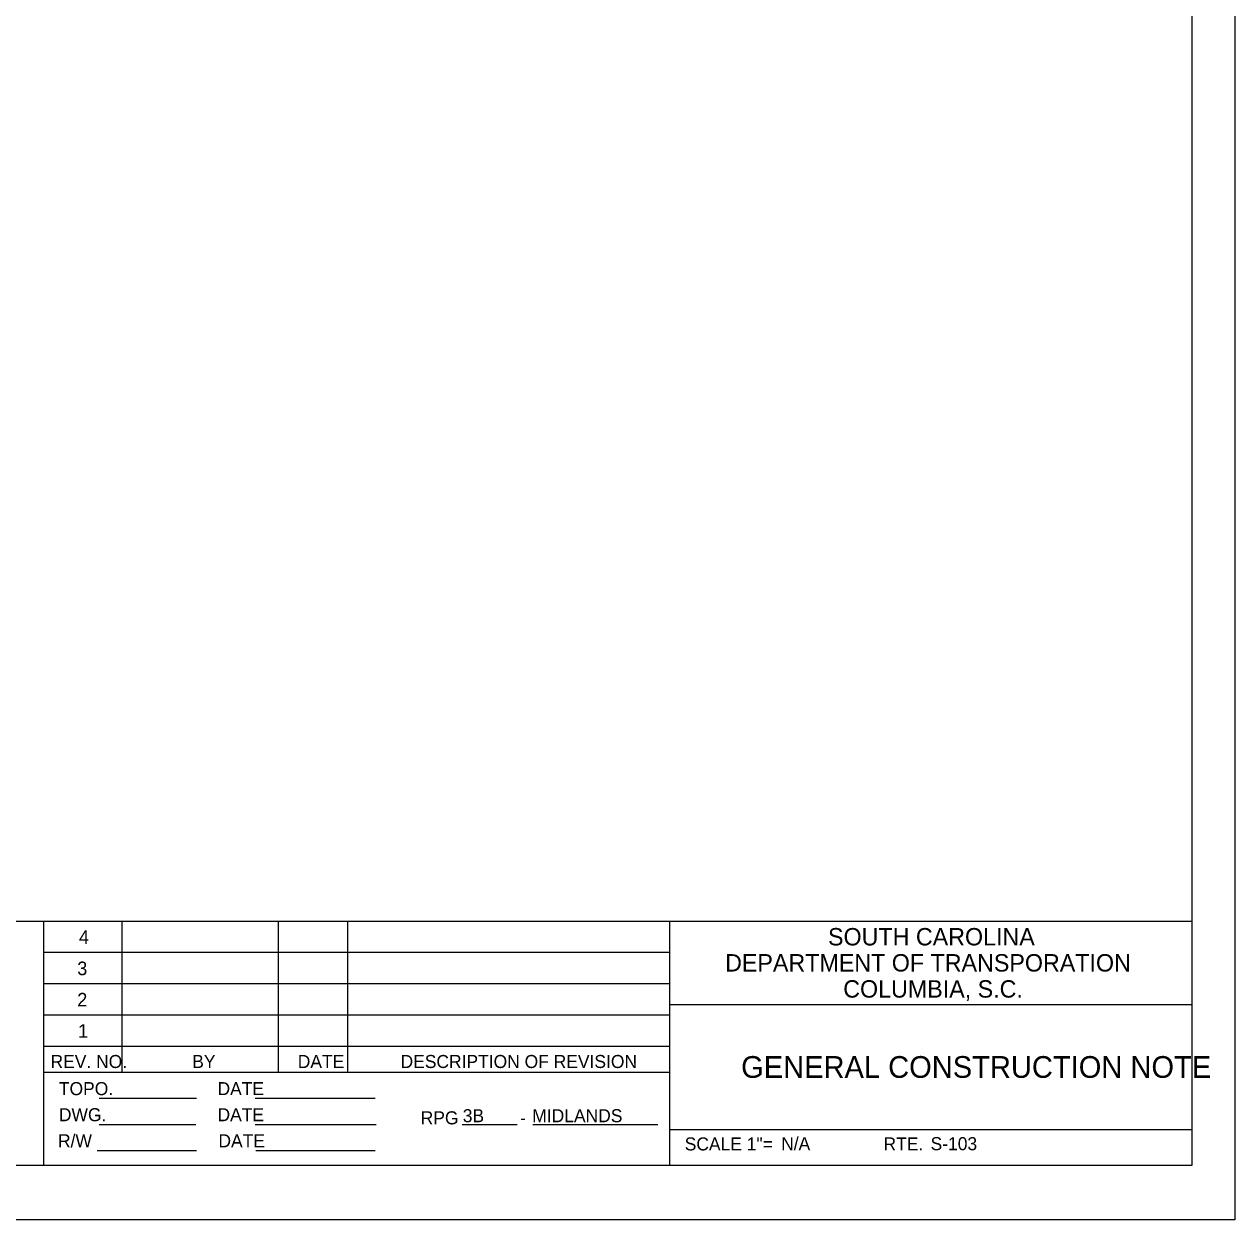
# Model space of a CAD drawing. Extents: x -796 to 2793, y -4650 to 4425.
# Drawn here: x 2221 to 2777, y -3500 to -2950 of the extents above; entities that cross this region are included whole.
import ezdxf

# ---------------------------------------------------------------- set-up
doc = ezdxf.new("R2010")
doc.units = 0
for name, color, linetype in [('RD_HC_CL', 7, 'Continuous'), ('RD_HC_Data', 7, 'Continuous'), ('RD_HC_Data_Tic', 7, 'Continuous')]:
    doc.layers.add(name, color=color, linetype=linetype)

msp = doc.modelspace()

# ---------------------------------------------------------------- linework, layer by layer
at = {"layer": 'RD_HC_CL'}
msp.add_lwpolyline([(981.4, -2400), (2777.4, -2400), (2777.4, -3500), (981.4, -3500)], close=True, dxfattribs=at)
at = {"layer": 'RD_HC_Data'}
for p, q in [((1995.01, -3362.55), (2757.6, -3362.55)), ((2229.59, -3475), (2229.59, -3362.55)), ((2229.59, -3362.55), (2229.59, -3362.55)), ((2265.59, -3432.24), (2265.59, -3362.55)), ((2337.59, -3432.24), (2337.59, -3362.55)), ((2369.41, -3432.1), (2369.41, -3362.5)), ((2517.59, -3475), (2517.59, -3362.55)), ((2229.59, -3376.9), (2517.59, -3376.9)), ((2229.59, -3391.3), (2517.59, -3391.3)), ((2517.59, -3400.9), (2757.6, -3400.9)), ((2229.59, -3405.7), (2517.59, -3405.7)), ((2229.59, -3420.1), (2517.59, -3420.1)), ((2229.59, -3432.1), (2517.59, -3432.1)), ((2255.03, -3444.1), (2299.91, -3444.1)), ((2326.79, -3444.1), (2382.08, -3444.1)), ((2255.03, -3456.1), (2299.52, -3456.1)), ((2326.79, -3456.1), (2382.51, -3456.1)), ((2422.11, -3456.1), (2447.32, -3456.1)), ((2454.51, -3456.1), (2512.02, -3456.1)), ((2517.59, -3458.5), (2757.6, -3458.5)), ((2254.21, -3468.1), (2299.91, -3468.1)), ((2327.17, -3468.1), (2382.08, -3468.1)), ((2760, -3500), (1000, -3500)), ((2760, -3500), (1000, -3500))]:
    msp.add_line(p, q, dxfattribs=at)
msp.add_lwpolyline([(1082.6, -2425), (2757.6, -2425), (2757.6, -3475), (1082.6, -3475)], close=True, dxfattribs=at)

# ---------------------------------------------------------------- texts
at = {"layer": 'RD_HC_Data_Tic'}
for s, height, p in [('4', 6.24, (2245.76, -3373.06)), ('SOUTH CAROLINA', 8, (2590.31, -3373.79)), ('DEPARTMENT OF TRANSPORATION', 8, (2542.97, -3385.79)), ('3', 6.24, (2244.99, -3387.46)), ('COLUMBIA, S.C.', 8, (2597.31, -3397.79)), ('2', 6.24, (2244.99, -3401.86)), ('1', 6.24, (2245.38, -3416.26)), ('REV. NO.', 6, (2232.71, -3430.18)), ('BY', 6, (2297.89, -3430.18)), ('DATE', 6, (2346.42, -3430.18)), ('DESCRIPTION OF REVISION', 6, (2393.7, -3430.18)), ('   GENERAL CONSTRUCTION NOTE   ', 10, (2539.2, -3434.7)), ('TOPO.', 6, (2236.55, -3442.66)), ('DATE', 6, (2309.51, -3442.66)), ('DWG.', 6, (2236.55, -3454.66)), ('DATE', 6, (2309.51, -3454.66)), ('RPG', 6, (2402.96, -3456.1)), ('3B    ', 6, (2422.31, -3455.12)), ('MIDLANDS   ', 6, (2454.29, -3455.12)), ('-', 6, (2448.7, -3456.1)), ('R/W', 6, (2236.16, -3466.66)), ('DATE', 6, (2309.94, -3466.66)), ('SCALE 1"=', 6, (2524.4, -3468.1)), ('N/A        ', 6, (2568.76, -3467.99)), ('RTE.', 6, (2615.84, -3468.1)), ('S-103      ', 6, (2637.49, -3467.99))]:
    msp.add_text(s, height=height, dxfattribs=at).set_placement(p)

doc.saveas('drawing.dxf')
